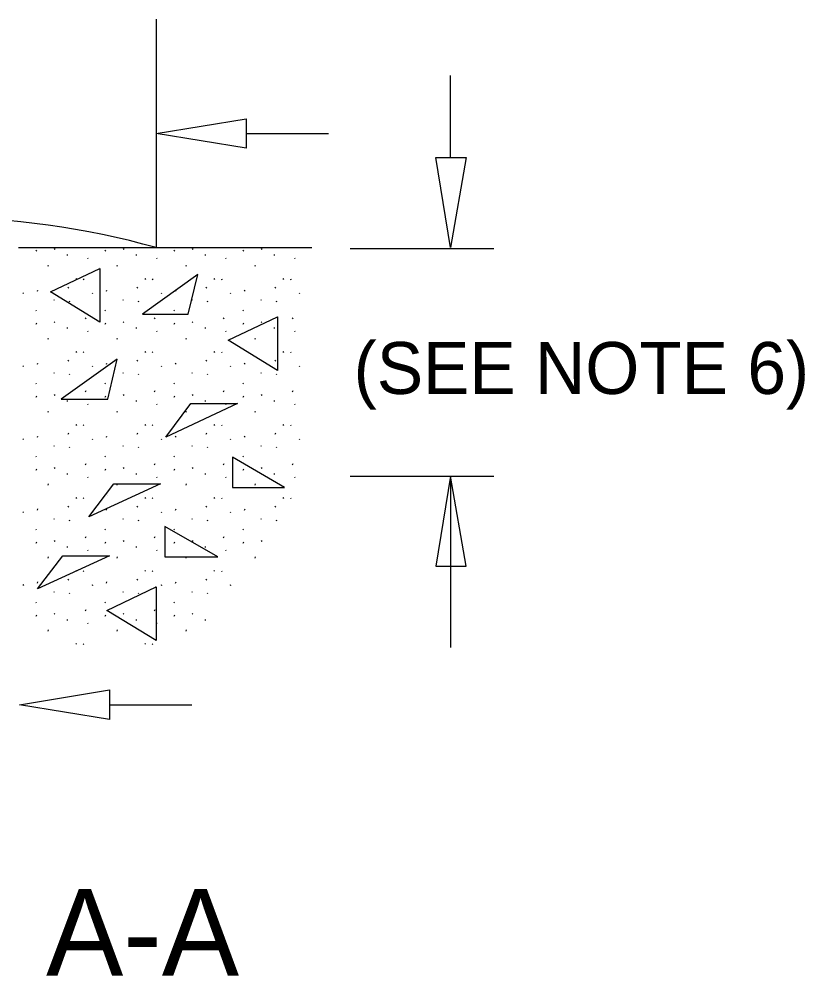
# Model space of a CAD drawing. Extents: x -1550.42 to -1543.2, y 2481.09 to 2491.
# Drawn here: x -1548.454 to -1547.547, y 2486.013 to 2487.119 of the extents above; entities that cross this region are included whole.
import ezdxf

# ---------------------------------------------------------------- set-up
doc = ezdxf.new("R2010")
doc.units = 0
for name, color, linetype in [('DETL-DIMS', 7, 'Continuous'), ('DETL-LINE', 7, 'Continuous'), ('DETL-NOTE', 7, 'Continuous'), ('DETL-PATT', 7, 'Continuous'), ('DETL-TITL', 7, 'Continuous')]:
    doc.layers.add(name, color=color, linetype=linetype)

msp = doc.modelspace()

# ---------------------------------------------------------------- linework, layer by layer
at = {"layer": 'DETL-DIMS'}
for p, q in [((-1548.296, 2487.119), (-1548.296, 2486.855)), ((-1547.956, 2486.959), (-1547.956, 2487.054)), ((-1548.192, 2486.987), (-1548.097, 2486.987)), ((-1548.072, 2486.854), (-1547.906, 2486.854)), ((-1548.072, 2486.591), (-1547.906, 2486.591)), ((-1547.956, 2486.591), (-1547.956, 2486.393)), ((-1548.35, 2486.327), (-1548.255, 2486.327))]:
    msp.add_line(p, q, dxfattribs=at)
for points in [[(-1548.192, 2487.004), (-1548.192, 2486.97), (-1548.296, 2486.987)], [(-1547.973, 2486.959), (-1547.938, 2486.959), (-1547.956, 2486.855)], [(-1547.973, 2486.487), (-1547.938, 2486.487), (-1547.956, 2486.591)], [(-1548.35, 2486.344), (-1548.35, 2486.31), (-1548.454, 2486.327)]]:
    msp.add_lwpolyline(points, close=True, dxfattribs=at)
at = {"layer": 'DETL-LINE'}
msp.add_line((-1548.455, 2486.855), (-1548.1162, 2486.855), dxfattribs=at)
msp.add_arc((-1548.5493, 2485.9521), 0.9378, 74.3295, 105.4426, dxfattribs=at)
at = {"layer": 'DETL-PATT'}
for p, q in [((-1548.4347, 2486.851), (-1548.4341, 2486.8523)), ((-1548.4139, 2486.8539), (-1548.4133, 2486.853)), ((-1548.399, 2486.8472), (-1548.3989, 2486.8458)), ((-1548.3549, 2486.851), (-1548.3543, 2486.8523)), ((-1548.3342, 2486.8539), (-1548.3336, 2486.853)), ((-1548.3193, 2486.8472), (-1548.3192, 2486.8458)), ((-1548.2752, 2486.851), (-1548.2746, 2486.8523)), ((-1548.2544, 2486.8539), (-1548.2538, 2486.853)), ((-1548.2396, 2486.8472), (-1548.2395, 2486.8458)), ((-1548.1955, 2486.851), (-1548.1949, 2486.8523)), ((-1548.1747, 2486.8539), (-1548.1741, 2486.853)), ((-1548.1599, 2486.8472), (-1548.1597, 2486.8458)), ((-1548.421, 2486.8336), (-1548.4204, 2486.8349)), ((-1548.3755, 2486.8432), (-1548.3749, 2486.8423)), ((-1548.3413, 2486.8336), (-1548.3407, 2486.8349)), ((-1548.2958, 2486.8432), (-1548.2952, 2486.8423)), ((-1548.2616, 2486.8336), (-1548.261, 2486.8349)), ((-1548.2161, 2486.8432), (-1548.2155, 2486.8423)), ((-1548.1819, 2486.8336), (-1548.1813, 2486.8349)), ((-1548.1364, 2486.8432), (-1548.1358, 2486.8423)), ((-1548.418, 2486.804), (-1548.361, 2486.831)), ((-1548.362, 2486.832), (-1548.362, 2486.832)), ((-1548.361, 2486.831), (-1548.361, 2486.769)), ((-1548.248, 2486.824), (-1548.312, 2486.778)), ((-1548.259, 2486.778), (-1548.248, 2486.824)), ((-1548.3888, 2486.8193), (-1548.3882, 2486.8184)), ((-1548.3803, 2486.8189), (-1548.3797, 2486.818)), ((-1548.3091, 2486.8193), (-1548.3085, 2486.8184)), ((-1548.3006, 2486.8189), (-1548.3, 2486.818)), ((-1548.2294, 2486.8193), (-1548.2288, 2486.8184)), ((-1548.2208, 2486.8189), (-1548.2202, 2486.818)), ((-1548.1497, 2486.8193), (-1548.1491, 2486.8184)), ((-1548.1411, 2486.8189), (-1548.1405, 2486.818)), ((-1548.4499, 2486.8029), (-1548.4493, 2486.8021)), ((-1548.4332, 2486.8047), (-1548.4326, 2486.806)), ((-1548.361, 2486.769), (-1548.418, 2486.804)), ((-1548.3977, 2486.8081), (-1548.3971, 2486.8095)), ((-1548.3702, 2486.8029), (-1548.3696, 2486.8021)), ((-1548.3535, 2486.8047), (-1548.3529, 2486.806)), ((-1548.3179, 2486.8081), (-1548.3173, 2486.8095)), ((-1548.2905, 2486.8029), (-1548.2899, 2486.8021)), ((-1548.2737, 2486.8047), (-1548.2731, 2486.806)), ((-1548.2382, 2486.8081), (-1548.2376, 2486.8095)), ((-1548.2108, 2486.8029), (-1548.2102, 2486.8021)), ((-1548.194, 2486.8047), (-1548.1934, 2486.806)), ((-1548.1585, 2486.8081), (-1548.1579, 2486.8095)), ((-1548.1311, 2486.8029), (-1548.1305, 2486.8021)), ((-1548.4144, 2486.7951), (-1548.4138, 2486.7942)), ((-1548.3967, 2486.7935), (-1548.3961, 2486.7926)), ((-1548.3347, 2486.7951), (-1548.3341, 2486.7942)), ((-1548.317, 2486.7935), (-1548.3164, 2486.7926)), ((-1548.255, 2486.7951), (-1548.2544, 2486.7942)), ((-1548.2373, 2486.7935), (-1548.2367, 2486.7926)), ((-1548.1753, 2486.7951), (-1548.1747, 2486.7942)), ((-1548.1576, 2486.7935), (-1548.157, 2486.7926)), ((-1548.4352, 2486.7828), (-1548.4346, 2486.7819)), ((-1548.3554, 2486.7828), (-1548.3548, 2486.7819)), ((-1548.312, 2486.778), (-1548.259, 2486.778)), ((-1548.2757, 2486.7828), (-1548.2751, 2486.7819)), ((-1548.196, 2486.7828), (-1548.1954, 2486.7819)), ((-1548.4347, 2486.7666), (-1548.4341, 2486.768)), ((-1548.4139, 2486.7695), (-1548.4133, 2486.7686)), ((-1548.3777, 2486.7728), (-1548.3771, 2486.7741)), ((-1548.3549, 2486.7666), (-1548.3543, 2486.768)), ((-1548.3342, 2486.7695), (-1548.3336, 2486.7686)), ((-1548.298, 2486.7728), (-1548.2974, 2486.7741)), ((-1548.2752, 2486.7666), (-1548.2746, 2486.768)), ((-1548.2544, 2486.7695), (-1548.2538, 2486.7686)), ((-1548.2183, 2486.7728), (-1548.2177, 2486.7741)), ((-1548.213, 2486.748), (-1548.156, 2486.775)), ((-1548.1955, 2486.7666), (-1548.1949, 2486.768)), ((-1548.1747, 2486.7695), (-1548.1741, 2486.7686)), ((-1548.156, 2486.776), (-1548.156, 2486.776)), ((-1548.156, 2486.775), (-1548.156, 2486.713)), ((-1548.1386, 2486.7728), (-1548.138, 2486.7741)), ((-1548.399, 2486.7629), (-1548.3989, 2486.7615)), ((-1548.3755, 2486.7589), (-1548.3749, 2486.758)), ((-1548.3193, 2486.7629), (-1548.3192, 2486.7615)), ((-1548.2958, 2486.7589), (-1548.2952, 2486.758)), ((-1548.2396, 2486.7629), (-1548.2395, 2486.7615)), ((-1548.2161, 2486.7589), (-1548.2155, 2486.758)), ((-1548.1599, 2486.7629), (-1548.1597, 2486.7615)), ((-1548.1364, 2486.7589), (-1548.1358, 2486.758)), ((-1548.421, 2486.7493), (-1548.4204, 2486.7506)), ((-1548.3413, 2486.7493), (-1548.3407, 2486.7506)), ((-1548.2616, 2486.7493), (-1548.261, 2486.7506)), ((-1548.156, 2486.713), (-1548.213, 2486.748)), ((-1548.1819, 2486.7493), (-1548.1813, 2486.7506)), ((-1548.3888, 2486.7349), (-1548.3882, 2486.734)), ((-1548.3803, 2486.7346), (-1548.3797, 2486.7337)), ((-1548.3091, 2486.7349), (-1548.3085, 2486.734)), ((-1548.3006, 2486.7346), (-1548.3, 2486.7337)), ((-1548.2294, 2486.7349), (-1548.2288, 2486.734)), ((-1548.2208, 2486.7346), (-1548.2202, 2486.7337)), ((-1548.1497, 2486.7349), (-1548.1491, 2486.734)), ((-1548.1411, 2486.7346), (-1548.1405, 2486.7337)), ((-1548.341, 2486.726), (-1548.406, 2486.68)), ((-1548.3977, 2486.7238), (-1548.3971, 2486.7252)), ((-1548.352, 2486.68), (-1548.341, 2486.726)), ((-1548.3179, 2486.7238), (-1548.3173, 2486.7252)), ((-1548.2382, 2486.7238), (-1548.2376, 2486.7252)), ((-1548.1585, 2486.7238), (-1548.1579, 2486.7252)), ((-1548.4499, 2486.7186), (-1548.4493, 2486.7177)), ((-1548.4332, 2486.7204), (-1548.4326, 2486.7217)), ((-1548.3702, 2486.7186), (-1548.3696, 2486.7177)), ((-1548.3535, 2486.7204), (-1548.3529, 2486.7217)), ((-1548.2905, 2486.7186), (-1548.2899, 2486.7177)), ((-1548.2737, 2486.7204), (-1548.2731, 2486.7217)), ((-1548.2108, 2486.7186), (-1548.2102, 2486.7177)), ((-1548.194, 2486.7204), (-1548.1934, 2486.7217)), ((-1548.1311, 2486.7186), (-1548.1305, 2486.7178)), ((-1548.4144, 2486.7108), (-1548.4138, 2486.7099)), ((-1548.3967, 2486.7092), (-1548.3961, 2486.7083)), ((-1548.3347, 2486.7108), (-1548.3341, 2486.7099)), ((-1548.317, 2486.7092), (-1548.3164, 2486.7083)), ((-1548.255, 2486.7108), (-1548.2544, 2486.7099)), ((-1548.2373, 2486.7092), (-1548.2367, 2486.7083)), ((-1548.1753, 2486.7108), (-1548.1747, 2486.7099)), ((-1548.1576, 2486.7092), (-1548.157, 2486.7083)), ((-1548.4352, 2486.6985), (-1548.4346, 2486.6976)), ((-1548.3777, 2486.6885), (-1548.3771, 2486.6898)), ((-1548.3554, 2486.6985), (-1548.3548, 2486.6976)), ((-1548.298, 2486.6885), (-1548.2974, 2486.6898)), ((-1548.2757, 2486.6985), (-1548.2751, 2486.6976)), ((-1548.2183, 2486.6885), (-1548.2177, 2486.6898)), ((-1548.196, 2486.6985), (-1548.1954, 2486.6976)), ((-1548.1386, 2486.6885), (-1548.138, 2486.6898)), ((-1548.4347, 2486.6823), (-1548.4341, 2486.6837)), ((-1548.4139, 2486.6852), (-1548.4133, 2486.6843)), ((-1548.406, 2486.68), (-1548.352, 2486.68)), ((-1548.399, 2486.6786), (-1548.3989, 2486.6772)), ((-1548.3549, 2486.6823), (-1548.3543, 2486.6837)), ((-1548.3342, 2486.6852), (-1548.3336, 2486.6843)), ((-1548.3193, 2486.6786), (-1548.3192, 2486.6772)), ((-1548.2752, 2486.6823), (-1548.2746, 2486.6837)), ((-1548.2544, 2486.6852), (-1548.2538, 2486.6843)), ((-1548.2396, 2486.6786), (-1548.2395, 2486.6772)), ((-1548.1955, 2486.6823), (-1548.1949, 2486.6837)), ((-1548.1747, 2486.6852), (-1548.1741, 2486.6843)), ((-1548.1599, 2486.6786), (-1548.1597, 2486.6772)), ((-1548.3755, 2486.6746), (-1548.3749, 2486.6737)), ((-1548.2958, 2486.6746), (-1548.2952, 2486.6737)), ((-1548.285, 2486.636), (-1548.256, 2486.675)), ((-1548.202, 2486.675), (-1548.285, 2486.636)), ((-1548.256, 2486.675), (-1548.202, 2486.675)), ((-1548.2161, 2486.6746), (-1548.2155, 2486.6737)), ((-1548.1364, 2486.6746), (-1548.1358, 2486.6737)), ((-1548.421, 2486.6649), (-1548.4204, 2486.6663)), ((-1548.3413, 2486.6649), (-1548.3407, 2486.6663)), ((-1548.2616, 2486.6649), (-1548.261, 2486.6663)), ((-1548.235, 2486.66), (-1548.235, 2486.66)), ((-1548.1819, 2486.6649), (-1548.1813, 2486.6663)), ((-1548.3888, 2486.6506), (-1548.3882, 2486.6497)), ((-1548.3803, 2486.6503), (-1548.3797, 2486.6494)), ((-1548.3091, 2486.6506), (-1548.3085, 2486.6497)), ((-1548.3006, 2486.6503), (-1548.3, 2486.6494)), ((-1548.2294, 2486.6506), (-1548.2288, 2486.6497)), ((-1548.2208, 2486.6503), (-1548.2202, 2486.6494)), ((-1548.1497, 2486.6506), (-1548.1491, 2486.6497)), ((-1548.1411, 2486.6503), (-1548.1405, 2486.6494)), ((-1548.4499, 2486.6343), (-1548.4493, 2486.6334)), ((-1548.4332, 2486.6361), (-1548.4326, 2486.6374)), ((-1548.3977, 2486.6395), (-1548.3971, 2486.6409)), ((-1548.3702, 2486.6343), (-1548.3696, 2486.6334)), ((-1548.3535, 2486.6361), (-1548.3529, 2486.6374)), ((-1548.3179, 2486.6395), (-1548.3173, 2486.6409)), ((-1548.2905, 2486.6343), (-1548.2899, 2486.6334)), ((-1548.2737, 2486.6361), (-1548.2731, 2486.6374)), ((-1548.2382, 2486.6395), (-1548.2376, 2486.6409)), ((-1548.2108, 2486.6343), (-1548.2102, 2486.6334)), ((-1548.194, 2486.6361), (-1548.1934, 2486.6374)), ((-1548.1585, 2486.6395), (-1548.1579, 2486.6409)), ((-1548.1311, 2486.6343), (-1548.1305, 2486.6335)), ((-1548.4144, 2486.6265), (-1548.4138, 2486.6256)), ((-1548.3967, 2486.6249), (-1548.3961, 2486.624)), ((-1548.3347, 2486.6265), (-1548.3341, 2486.6256)), ((-1548.317, 2486.6249), (-1548.3164, 2486.624)), ((-1548.255, 2486.6265), (-1548.2544, 2486.6256)), ((-1548.2373, 2486.6249), (-1548.2367, 2486.624)), ((-1548.1753, 2486.6265), (-1548.1747, 2486.6256)), ((-1548.1576, 2486.6249), (-1548.157, 2486.624)), ((-1548.4352, 2486.6142), (-1548.4346, 2486.6133)), ((-1548.3554, 2486.6142), (-1548.3548, 2486.6133)), ((-1548.2757, 2486.6142), (-1548.2751, 2486.6133)), ((-1548.208, 2486.613), (-1548.208, 2486.578)), ((-1548.148, 2486.578), (-1548.208, 2486.613)), ((-1548.196, 2486.6142), (-1548.1954, 2486.6133)), ((-1548.4139, 2486.6009), (-1548.4133, 2486.6)), ((-1548.3777, 2486.6042), (-1548.3771, 2486.6055)), ((-1548.3342, 2486.6009), (-1548.3336, 2486.6)), ((-1548.298, 2486.6042), (-1548.2974, 2486.6055)), ((-1548.2544, 2486.6009), (-1548.2538, 2486.6)), ((-1548.2183, 2486.6042), (-1548.2177, 2486.6055)), ((-1548.1747, 2486.6009), (-1548.1741, 2486.6)), ((-1548.1386, 2486.6042), (-1548.138, 2486.6055)), ((-1548.4347, 2486.598), (-1548.4341, 2486.5994)), ((-1548.399, 2486.5942), (-1548.3989, 2486.5929)), ((-1548.3755, 2486.5903), (-1548.3749, 2486.5894)), ((-1548.3549, 2486.598), (-1548.3543, 2486.5994)), ((-1548.3193, 2486.5942), (-1548.3192, 2486.5929)), ((-1548.2958, 2486.5903), (-1548.2952, 2486.5894)), ((-1548.2752, 2486.598), (-1548.2746, 2486.5994)), ((-1548.2396, 2486.5942), (-1548.2395, 2486.5929)), ((-1548.2161, 2486.5903), (-1548.2155, 2486.5894)), ((-1548.1955, 2486.598), (-1548.1949, 2486.5994)), ((-1548.1599, 2486.5942), (-1548.1597, 2486.5929)), ((-1548.1364, 2486.5903), (-1548.1358, 2486.5894)), ((-1548.421, 2486.5806), (-1548.4204, 2486.582)), ((-1548.291, 2486.582), (-1548.374, 2486.544)), ((-1548.374, 2486.544), (-1548.345, 2486.582)), ((-1548.345, 2486.582), (-1548.291, 2486.582)), ((-1548.3413, 2486.5806), (-1548.3407, 2486.582)), ((-1548.2616, 2486.5806), (-1548.261, 2486.582)), ((-1548.1819, 2486.5806), (-1548.1813, 2486.582)), ((-1548.352, 2486.569), (-1548.352, 2486.569)), ((-1548.208, 2486.578), (-1548.148, 2486.578)), ((-1548.3977, 2486.5552), (-1548.3971, 2486.5565)), ((-1548.3888, 2486.5663), (-1548.3882, 2486.5654)), ((-1548.3803, 2486.566), (-1548.3797, 2486.5651)), ((-1548.3179, 2486.5552), (-1548.3173, 2486.5565)), ((-1548.3091, 2486.5663), (-1548.3085, 2486.5654)), ((-1548.3006, 2486.566), (-1548.3, 2486.5651)), ((-1548.2382, 2486.5552), (-1548.2376, 2486.5565)), ((-1548.2294, 2486.5663), (-1548.2288, 2486.5654)), ((-1548.2208, 2486.566), (-1548.2202, 2486.5651)), ((-1548.1585, 2486.5552), (-1548.1579, 2486.5565)), ((-1548.1497, 2486.5663), (-1548.1491, 2486.5654)), ((-1548.1411, 2486.566), (-1548.1405, 2486.5651)), ((-1548.4499, 2486.55), (-1548.4493, 2486.5491)), ((-1548.4332, 2486.5518), (-1548.4326, 2486.5531)), ((-1548.3702, 2486.55), (-1548.3696, 2486.5491)), ((-1548.3535, 2486.5518), (-1548.3529, 2486.5531)), ((-1548.2905, 2486.55), (-1548.2899, 2486.5491)), ((-1548.2737, 2486.5518), (-1548.2731, 2486.5531)), ((-1548.2108, 2486.55), (-1548.2102, 2486.5491)), ((-1548.194, 2486.5518), (-1548.1934, 2486.5531)), ((-1548.4144, 2486.5422), (-1548.4138, 2486.5413)), ((-1548.3967, 2486.5405), (-1548.3961, 2486.5396)), ((-1548.3347, 2486.5422), (-1548.3341, 2486.5413)), ((-1548.317, 2486.5405), (-1548.3164, 2486.5396)), ((-1548.255, 2486.5422), (-1548.2544, 2486.5413)), ((-1548.2373, 2486.5405), (-1548.2367, 2486.5396)), ((-1548.1753, 2486.5422), (-1548.1747, 2486.5413)), ((-1548.1576, 2486.5405), (-1548.157, 2486.5396)), ((-1548.4352, 2486.5299), (-1548.4346, 2486.529)), ((-1548.3554, 2486.5299), (-1548.3548, 2486.529)), ((-1548.286, 2486.533), (-1548.286, 2486.498)), ((-1548.225, 2486.498), (-1548.286, 2486.533)), ((-1548.286, 2486.53), (-1548.286, 2486.53)), ((-1548.2757, 2486.5299), (-1548.2751, 2486.529)), ((-1548.196, 2486.5299), (-1548.1954, 2486.529)), ((-1548.4347, 2486.5137), (-1548.4341, 2486.515)), ((-1548.4139, 2486.5166), (-1548.4133, 2486.5157)), ((-1548.3777, 2486.5198), (-1548.3771, 2486.5212)), ((-1548.3549, 2486.5137), (-1548.3543, 2486.515)), ((-1548.3342, 2486.5166), (-1548.3336, 2486.5157)), ((-1548.298, 2486.5198), (-1548.2974, 2486.5212)), ((-1548.2752, 2486.5137), (-1548.2746, 2486.515)), ((-1548.2544, 2486.5166), (-1548.2538, 2486.5157)), ((-1548.2183, 2486.5198), (-1548.2177, 2486.5212)), ((-1548.1955, 2486.5137), (-1548.1949, 2486.515)), ((-1548.1747, 2486.5166), (-1548.1741, 2486.5157)), ((-1548.399, 2486.5099), (-1548.3989, 2486.5086)), ((-1548.3755, 2486.506), (-1548.3749, 2486.5051)), ((-1548.3193, 2486.5099), (-1548.3192, 2486.5086)), ((-1548.2958, 2486.506), (-1548.2952, 2486.5051)), ((-1548.2396, 2486.5099), (-1548.2395, 2486.5086)), ((-1548.2161, 2486.506), (-1548.2155, 2486.5051)), ((-1548.35, 2486.499), (-1548.433, 2486.461)), ((-1548.433, 2486.461), (-1548.404, 2486.499)), ((-1548.421, 2486.4963), (-1548.4204, 2486.4977)), ((-1548.404, 2486.499), (-1548.35, 2486.499)), ((-1548.3413, 2486.4963), (-1548.3407, 2486.4977)), ((-1548.286, 2486.498), (-1548.225, 2486.498)), ((-1548.2616, 2486.4963), (-1548.261, 2486.4977)), ((-1548.1819, 2486.4963), (-1548.1813, 2486.4977)), ((-1548.3888, 2486.482), (-1548.3882, 2486.4811)), ((-1548.3803, 2486.4817), (-1548.3797, 2486.4808)), ((-1548.3091, 2486.482), (-1548.3085, 2486.4811)), ((-1548.3006, 2486.4817), (-1548.3, 2486.4808)), ((-1548.2294, 2486.482), (-1548.2288, 2486.4811)), ((-1548.2208, 2486.4817), (-1548.2202, 2486.4808)), ((-1548.4332, 2486.4674), (-1548.4326, 2486.4688)), ((-1548.3977, 2486.4709), (-1548.3971, 2486.4722)), ((-1548.3535, 2486.4674), (-1548.3529, 2486.4688)), ((-1548.3179, 2486.4709), (-1548.3173, 2486.4722)), ((-1548.2737, 2486.4674), (-1548.2731, 2486.4688)), ((-1548.2382, 2486.4709), (-1548.2376, 2486.4722)), ((-1548.4499, 2486.4657), (-1548.4493, 2486.4648)), ((-1548.4144, 2486.4578), (-1548.4138, 2486.4569)), ((-1548.3702, 2486.4657), (-1548.3696, 2486.4648)), ((-1548.353, 2486.436), (-1548.296, 2486.463)), ((-1548.3347, 2486.4578), (-1548.3341, 2486.4569)), ((-1548.297, 2486.464), (-1548.297, 2486.464)), ((-1548.296, 2486.463), (-1548.296, 2486.401)), ((-1548.2905, 2486.4657), (-1548.2899, 2486.4648)), ((-1548.255, 2486.4578), (-1548.2544, 2486.4569)), ((-1548.2108, 2486.4657), (-1548.2102, 2486.4648)), ((-1548.4352, 2486.4456), (-1548.4346, 2486.4447)), ((-1548.3967, 2486.4562), (-1548.3961, 2486.4553)), ((-1548.3554, 2486.4456), (-1548.3548, 2486.4447)), ((-1548.317, 2486.4562), (-1548.3164, 2486.4553)), ((-1548.2757, 2486.4456), (-1548.2751, 2486.4447)), ((-1548.2373, 2486.4562), (-1548.2367, 2486.4553)), ((-1548.3777, 2486.4355), (-1548.3771, 2486.4369)), ((-1548.296, 2486.401), (-1548.353, 2486.436)), ((-1548.298, 2486.4355), (-1548.2974, 2486.4369)), ((-1548.4347, 2486.4294), (-1548.4341, 2486.4307)), ((-1548.4139, 2486.4323), (-1548.4133, 2486.4314)), ((-1548.399, 2486.4256), (-1548.3989, 2486.4243)), ((-1548.3549, 2486.4294), (-1548.3543, 2486.4307)), ((-1548.3342, 2486.4323), (-1548.3336, 2486.4314)), ((-1548.3193, 2486.4256), (-1548.3192, 2486.4243)), ((-1548.2752, 2486.4294), (-1548.2746, 2486.4307)), ((-1548.2544, 2486.4323), (-1548.2538, 2486.4314)), ((-1548.2396, 2486.4256), (-1548.2395, 2486.4243)), ((-1548.421, 2486.412), (-1548.4204, 2486.4133)), ((-1548.3755, 2486.4216), (-1548.3749, 2486.4207)), ((-1548.3413, 2486.412), (-1548.3407, 2486.4133)), ((-1548.2958, 2486.4216), (-1548.2952, 2486.4207)), ((-1548.2616, 2486.412), (-1548.261, 2486.4133)), ((-1548.3888, 2486.3977), (-1548.3882, 2486.3968)), ((-1548.3803, 2486.3973), (-1548.3797, 2486.3964)), ((-1548.3091, 2486.3977), (-1548.3085, 2486.3968)), ((-1548.3006, 2486.3973), (-1548.3, 2486.3964))]:
    msp.add_line(p, q, dxfattribs=at)

# ---------------------------------------------------------------- texts
at = {"layer": 'DETL-NOTE'}
msp.add_text('(SEE NOTE 6)', height=0.06, dxfattribs=at).set_placement((-1548.068, 2486.686))
at = {"layer": 'DETL-TITL'}
msp.add_text('SECTION A-A', height=0.100002, dxfattribs=at).set_placement((-1549.0548, 2486.014))

doc.saveas('drawing.dxf')
